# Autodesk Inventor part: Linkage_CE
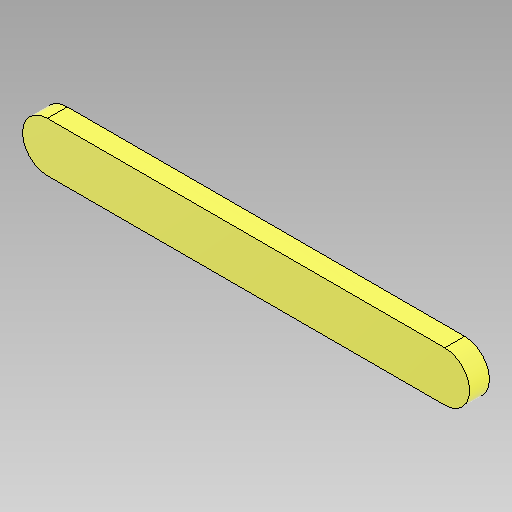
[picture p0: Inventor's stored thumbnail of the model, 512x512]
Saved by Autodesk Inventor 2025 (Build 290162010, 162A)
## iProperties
Created: 2024-10
Part Number: Linkage_CE
Material: Generic
Document SubType Name: Modeling
Designer: Dennis
Density: 1 g/cm^3
Appearance: Smooth - Yellow
Mass: 0.43927 g
Surface Area: 6.30686 cm^2
Volume: 0.43927 cm^3
Author: Dennis
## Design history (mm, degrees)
sketch "Sketch1"
  geometry: L1 (0, 0)-(40, 0); L2 (0, -2.5)-(40, -2.5); L3 (40, 2.5)-(0, 2.5); A1 r 2.5 centre (0, 0) between (0, 2.5) and (0, -2.5); A2 r 2.5 centre (40, 0) between (40, -2.5) and (40, 2.5); 1 further point
  constraints: 8 end point, 4 point on circle, 4 tangent, 2 centre point, 1 horizontal, 1 midpoint, 1 parallel
  dimensions: "d0" = 5 distance between parallel lines of L2 L3 (= w_); "d1" = 40 distance of L1.start L1.end (= CE_)
extrude "Extrusion1" new body sketch "Sketch1" stored distance "d2" = 2 (= t_); taper "d3" = 0 deg
body "Solid1"
other parameters: "CE_" = 40 [user parameter; used in 1 equation term], "w_" = 5 [user parameter; used in 1 equation term], "t_" = 2 [user parameter; used in 1 equation term]
